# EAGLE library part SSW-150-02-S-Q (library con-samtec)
THROUGH-HOLE .025" SQ POST SOCKET Source: Samtec SSW.pdf
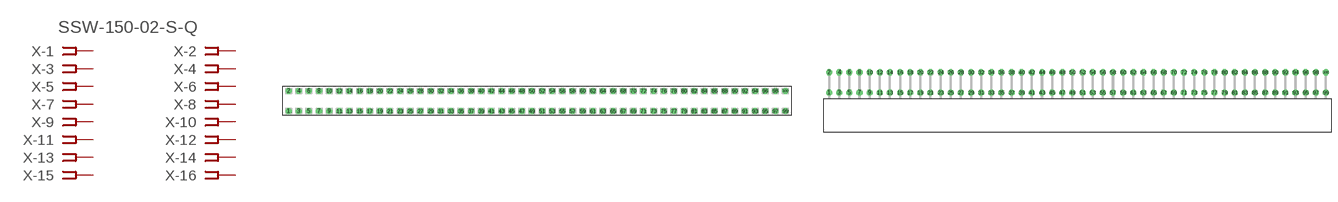
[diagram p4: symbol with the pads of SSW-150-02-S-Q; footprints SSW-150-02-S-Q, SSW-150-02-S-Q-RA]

Designator prefix X; gates -1=FPINV -2=FPIN -3=FPIN -4=FPIN -5=FPIN -6=FPIN -7=FPIN -8=FPIN -9=FPIN -10=FPIN -11=FPIN -12=FPIN -13=FPIN -14=FPIN -15=FPIN -16=FPIN -17=FPIN -18=FPIN -19=FPIN -20=FPIN -21=FPIN -22=FPIN -23=FPIN -24=FPIN -25=FPIN -26=FPIN -27=FPIN -28=FPIN -29=FPIN -30=FPIN -31=FPIN -32=FPIN -33=FPIN -34=FPIN -35=FPIN -36=FPIN -37=FPIN -38=FPIN -39=FPIN -40=FPIN -41=FPIN -42=FPIN -43=FPIN -44=FPIN -45=FPIN -46=FPIN -47=FPIN -48=FPIN -49=FPIN -50=FPIN -51=FPIN -52=FPIN -53=FPIN -54=FPIN -55=FPIN -56=FPIN -57=FPIN -58=FPIN -59=FPIN -60=FPIN -61=FPIN -62=FPIN -63=FPIN -64=FPIN -65=FPIN -66=FPIN -67=FPIN -68=FPIN -69=FPIN -70=FPIN -71=FPIN -72=FPIN -73=FPIN -74=FPIN -75=FPIN -76=FPIN -77=FPIN -78=FPIN -79=FPIN -80=FPIN -81=FPIN -82=FPIN -83=FPIN -84=FPIN -85=FPIN -86=FPIN -87=FPIN -88=FPIN -89=FPIN -90=FPIN -91=FPIN -92=FPIN -93=FPIN -94=FPIN -95=FPIN -96=FPIN -97=FPIN -98=FPIN -99=FPIN -100=FPIN

## SSW-150-02-S-Q (MPN: SSW-150-02-S-Q; OC_FARNELL: unknown; OC_NEWARK: 83P1895)  [SSW-150-02-S-Q]
1  -1:1  pas
2  -2:1  pas
3  -3:1  pas
4  -4:1  pas
5  -5:1  pas
6  -6:1  pas
7  -7:1  pas
8  -8:1  pas
9  -9:1  pas
10  -10:1  pas
11  -11:1  pas
12  -12:1  pas
13  -13:1  pas
14  -14:1  pas
15  -15:1  pas
16  -16:1  pas
17  -17:1  pas
18  -18:1  pas
19  -19:1  pas
20  -20:1  pas
21  -21:1  pas
22  -22:1  pas
23  -23:1  pas
24  -24:1  pas
25  -25:1  pas
26  -26:1  pas
27  -27:1  pas
28  -28:1  pas
29  -29:1  pas
30  -30:1  pas
31  -31:1  pas
32  -32:1  pas
33  -33:1  pas
34  -34:1  pas
35  -35:1  pas
36  -36:1  pas
37  -37:1  pas
38  -38:1  pas
39  -39:1  pas
40  -40:1  pas
41  -41:1  pas
42  -42:1  pas
43  -43:1  pas
44  -44:1  pas
45  -45:1  pas
46  -46:1  pas
47  -47:1  pas
48  -48:1  pas
49  -49:1  pas
50  -50:1  pas
51  -51:1  pas
52  -52:1  pas
53  -53:1  pas
54  -54:1  pas
55  -55:1  pas
56  -56:1  pas
57  -57:1  pas
58  -58:1  pas
59  -59:1  pas
60  -60:1  pas
61  -61:1  pas
62  -62:1  pas
63  -63:1  pas
64  -64:1  pas
65  -65:1  pas
66  -66:1  pas
67  -67:1  pas
68  -68:1  pas
69  -69:1  pas
70  -70:1  pas
71  -71:1  pas
72  -72:1  pas
73  -73:1  pas
74  -74:1  pas
75  -75:1  pas
76  -76:1  pas
77  -77:1  pas
78  -78:1  pas
79  -79:1  pas
80  -80:1  pas
81  -81:1  pas
82  -82:1  pas
83  -83:1  pas
84  -84:1  pas
85  -85:1  pas
86  -86:1  pas
87  -87:1  pas
88  -88:1  pas
89  -89:1  pas
90  -90:1  pas
91  -91:1  pas
92  -92:1  pas
93  -93:1  pas
94  -94:1  pas
95  -95:1  pas
96  -96:1  pas
97  -97:1  pas
98  -98:1  pas
99  -99:1  pas
100  -100:1  pas

## SSW-150-02-S-QRA (MPN: SSW-150-02-S-Q-RA; OC_FARNELL: unknown; OC_NEWARK: 83P1896)  [SSW-150-02-S-Q-RA]
Pads as for SSW-150-02-S-Q

## Footprint SSW-150-02-S-Q (pad centres in mm)
THROUGH-HOLE .025" SQ POST SOCKET Source: Samtec SSW.pdf
drill 1 pad 1.5 octagon: 1 -62.23,-2.54; 2 -62.23,2.54; 3 -59.69,-2.54; 4 -59.69,2.54; 5 -57.15,-2.54; 6 -57.15,2.54; 7 -54.61,-2.54; 8 -54.61,2.54; 9 -52.07,-2.54; 10 -52.07,2.54; 11 -49.53,-2.54; 12 -49.53,2.54; 13 -46.99,-2.54; 14 -46.99,2.54; 15 -44.45,-2.54; 16 -44.45,2.54; 17 -41.91,-2.54; 18 -41.91,2.54; 19 -39.37,-2.54; 20 -39.37,2.54; 21 -36.83,-2.54; 22 -36.83,2.54; 23 -34.29,-2.54; 24 -34.29,2.54; 25 -31.75,-2.54; 26 -31.75,2.54; 27 -29.21,-2.54; 28 -29.21,2.54; 29 -26.67,-2.54; 30 -26.67,2.54; 31 -24.13,-2.54; 32 -24.13,2.54; 33 -21.59,-2.54; 34 -21.59,2.54; 35 -19.05,-2.54; 36 -19.05,2.54; 37 -16.51,-2.54; 38 -16.51,2.54; 39 -13.97,-2.54; 40 -13.97,2.54; 41 -11.43,-2.54; 42 -11.43,2.54; 43 -8.89,-2.54; 44 -8.89,2.54; 45 -6.35,-2.54; 46 -6.35,2.54; 47 -3.81,-2.54; 48 -3.81,2.54; 49 -1.27,-2.54; 50 -1.27,2.54; 51 1.27,-2.54; 52 1.27,2.54; 53 3.81,-2.54; 54 3.81,2.54; 55 6.35,-2.54; 56 6.35,2.54; 57 8.89,-2.54; 58 8.89,2.54; 59 11.43,-2.54; 60 11.43,2.54; 61 13.97,-2.54; 62 13.97,2.54; 63 16.51,-2.54; 64 16.51,2.54; 65 19.05,-2.54; 66 19.05,2.54; 67 21.59,-2.54; 68 21.59,2.54; 69 24.13,-2.54; 70 24.13,2.54; 71 26.67,-2.54; 72 26.67,2.54; 73 29.21,-2.54; 74 29.21,2.54; 75 31.75,-2.54; 76 31.75,2.54; 77 34.29,-2.54; 78 34.29,2.54; 79 36.83,-2.54; 80 36.83,2.54; 81 39.37,-2.54; 82 39.37,2.54; 83 41.91,-2.54; 84 41.91,2.54; 85 44.45,-2.54; 86 44.45,2.54; 87 46.99,-2.54; 88 46.99,2.54; 89 49.53,-2.54; 90 49.53,2.54; 91 52.07,-2.54; 92 52.07,2.54; 93 54.61,-2.54; 94 54.61,2.54; 95 57.15,-2.54; 96 57.15,2.54; 97 59.69,-2.54; 98 59.69,2.54; 99 62.23,-2.54; 100 62.23,2.54

## Footprint SSW-150-02-S-Q-RA (pad centres in mm)
THROUGH-HOLE .025" SQ POST SOCKET Source: Samtec SSW.pdf
drill 1 pad 1.5 octagon: 1 -62.23,1.524; 2 -62.23,6.604; 3 -59.69,1.524; 4 -59.69,6.604; 5 -57.15,1.524; 6 -57.15,6.604; 7 -54.61,1.524; 8 -54.61,6.604; 9 -52.07,1.524; 10 -52.07,6.604; 11 -49.53,1.524; 12 -49.53,6.604; 13 -46.99,1.524; 14 -46.99,6.604; 15 -44.45,1.524; 16 -44.45,6.604; 17 -41.91,1.524; 18 -41.91,6.604; 19 -39.37,1.524; 20 -39.37,6.604; 21 -36.83,1.524; 22 -36.83,6.604; 23 -34.29,1.524; 24 -34.29,6.604; 25 -31.75,1.524; 26 -31.75,6.604; 27 -29.21,1.524; 28 -29.21,6.604; 29 -26.67,1.524; 30 -26.67,6.604; 31 -24.13,1.524; 32 -24.13,6.604; 33 -21.59,1.524; 34 -21.59,6.604; 35 -19.05,1.524; 36 -19.05,6.604; 37 -16.51,1.524; 38 -16.51,6.604; 39 -13.97,1.524; 40 -13.97,6.604; 41 -11.43,1.524; 42 -11.43,6.604; 43 -8.89,1.524; 44 -8.89,6.604; 45 -6.35,1.524; 46 -6.35,6.604; 47 -3.81,1.524; 48 -3.81,6.604; 49 -1.27,1.524; 50 -1.27,6.604; 51 1.27,1.524; 52 1.27,6.604; 53 3.81,1.524; 54 3.81,6.604; 55 6.35,1.524; 56 6.35,6.604; 57 8.89,1.524; 58 8.89,6.604; 59 11.43,1.524; 60 11.43,6.604; 61 13.97,1.524; 62 13.97,6.604; 63 16.51,1.524; 64 16.51,6.604; 65 19.05,1.524; 66 19.05,6.604; 67 21.59,1.524; 68 21.59,6.604; 69 24.13,1.524; 70 24.13,6.604; 71 26.67,1.524; 72 26.67,6.604; 73 29.21,1.524; 74 29.21,6.604; 75 31.75,1.524; 76 31.75,6.604; 77 34.29,1.524; 78 34.29,6.604; 79 36.83,1.524; 80 36.83,6.604; 81 39.37,1.524; 82 39.37,6.604; 83 41.91,1.524; 84 41.91,6.604; 85 44.45,1.524; 86 44.45,6.604; 87 46.99,1.524; 88 46.99,6.604; 89 49.53,1.524; 90 49.53,6.604; 91 52.07,1.524; 92 52.07,6.604; 93 54.61,1.524; 94 54.61,6.604; 95 57.15,1.524; 96 57.15,6.604; 97 59.69,1.524; 98 59.69,6.604; 99 62.23,1.524; 100 62.23,6.604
